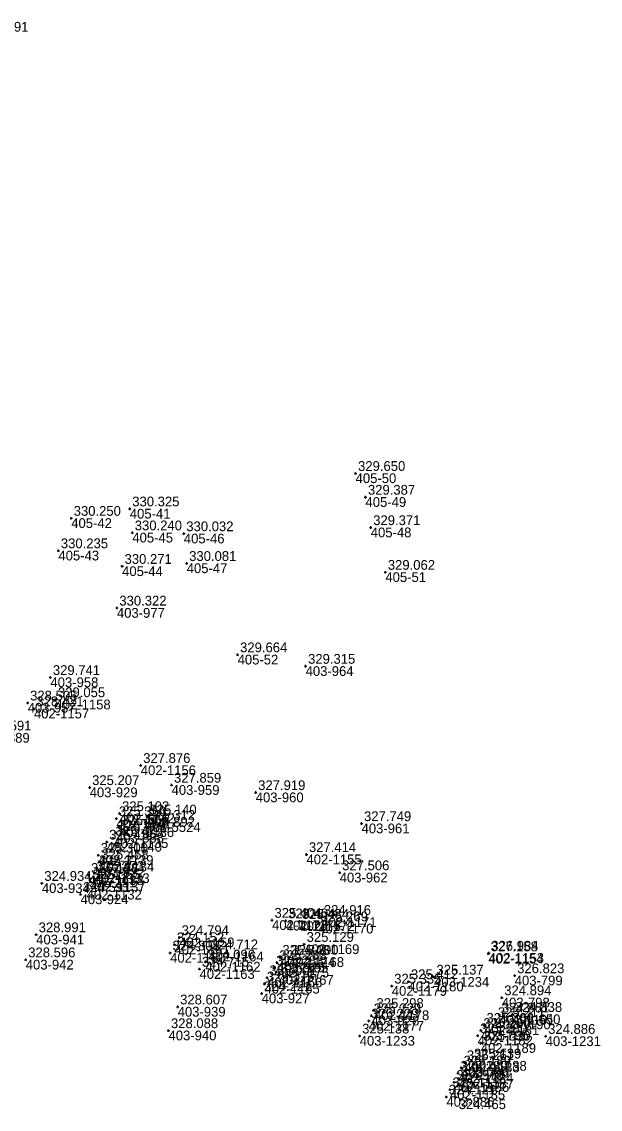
# Model space of a CAD drawing. Extents: x -829398 to -819400, y -1074439 to -1067977.
# Drawn here: x -824965 to -824893.9, y -1069611.4 to -1069477.7 of the extents above; entities that cross this region are included whole.
import ezdxf

# ---------------------------------------------------------------- set-up
doc = ezdxf.new("R2010")
doc.units = 0
for name, color, linetype in [('Vrstva 60', 7, 'Continuous'), ('Vrstva 61', 7, 'Continuous'), ('Čísla bodů_doměření_2012', 7, 'Continuous')]:
    doc.layers.add(name, color=color, linetype=linetype)

# ---------------------------------------------------------------- blocks, each defined once
blk = doc.blocks.new('BOD')
at = {"layer": 'Čísla bodů_doměření_2012'}
for p, q in [((-0.15, 0), (0.15, 0)), ((0, -0.15), (0, 0.15))]:
    blk.add_line(p, q, dxfattribs=at)

msp = doc.modelspace()

# ---------------------------------------------------------------- block references
at = {"layer": 'Vrstva 60'}
for p in [(-824923.944, -1069533.21), (-824922.729, -1069536.135), (-824958.89, -1069538.73), (-824951.691, -1069537.572), (-824922.083, -1069539.875), (-824951.381, -1069540.515), (-824945.052, -1069540.624), (-824960.463, -1069542.719), (-824952.636, -1069544.64), (-824944.7, -1069544.279), (-824920.286, -1069545.369), (-824953.277, -1069549.767), (-824938.442, -1069555.51), (-824930.086, -1069556.926), (-824961.447, -1069558.303), (-824964.242, -1069561.439), (-824960.823, -1069561.033), (-824963.47, -1069562.149), (-824950.345, -1069569.12), (-824956.625, -1069571.838), (-824946.56, -1069571.547), (-824936.219, -1069572.457), (-824953.341, -1069575.664), (-824952.944, -1069575.044), (-824949.774, -1069576.106), (-824949.576, -1069575.457), (-824953.388, -1069577.41), (-824953.034, -1069576.735), (-824923.214, -1069576.272), (-824954.522, -1069578.541), (-824953.741, -1069578.084), (-824955.565, -1069580.17), (-824929.983, -1069580.079), (-824955.475, -1069580.969), (-824956.756, -1069582.639), (-824956.044, -1069582.392), (-824955.76, -1069581.68), (-824925.9, -1069582.316), (-824962.497, -1069583.62), (-824956.541, -1069583.396), (-824957.741, -1069584.984), (-824956.997, -1069584.415), (-824934.213, -1069588.158), (-824928.152, -1069587.802), (-824932.533, -1069588.225), (-824930.853, -1069588.292), (-824928.536, -1069588.591), (-824963.195, -1069589.937), (-824945.617, -1069590.291), (-824946.738, -1069592.18), (-824946.201, -1069591.163), (-824942.036, -1069592.036), (-824930.263, -1069591.121), (-824907.572, -1069592.2), (-824964.477, -1069593.021), (-824942.41, -1069593.281), (-824933.614, -1069593.358), (-824933.239, -1069592.71), (-824932.148, -1069592.708), (-824907.644, -1069592.285), (-824943.126, -1069594.172), (-824933.988, -1069594.006), (-824933.416, -1069594.896), (-824935.137, -1069595.98), (-824934.822, -1069595.217), (-824917.445, -1069595.709), (-824914.307, -1069595.146), (-824904.394, -1069594.974), (-824935.487, -1069597.175), (-824919.498, -1069596.252), (-824945.809, -1069598.814), (-824905.979, -1069597.689), (-824922, -1069599.898), (-824921.678, -1069599.247), (-824906.271, -1069599.808), (-824904.667, -1069599.737), (-824922.323, -1069600.549), (-824908.159, -1069601.072), (-824906.759, -1069600.371), (-824946.936, -1069601.73), (-824923.443, -1069602.39), (-824908.945, -1069602.351), (-824908.552, -1069601.712), (-824900.587, -1069602.436), (-824908.56, -1069603.274), (-824909.692, -1069605.464), (-824910.963, -1069606.314), (-824910.571, -1069605.661), (-824911.848, -1069608.088), (-824911.355, -1069606.967), (-824911.277, -1069607.669), (-824912.35, -1069609.003), (-824912.789, -1069609.885)]:
    msp.add_blockref('BOD', p, dxfattribs=at)

# ---------------------------------------------------------------- texts
for s, p in [('405-50', (-824923.944, -1069534.41)), ('405-49', (-824922.729, -1069537.335)), ('405-41', (-824951.691, -1069538.772)), ('405-42', (-824958.89, -1069539.93)), ('405-48', (-824922.083, -1069541.075)), ('405-45', (-824951.381, -1069541.715)), ('405-46', (-824945.052, -1069541.824)), ('405-43', (-824960.463, -1069543.919)), ('405-44', (-824952.636, -1069545.84)), ('405-47', (-824944.7, -1069545.479)), ('405-51', (-824920.286, -1069546.569)), ('403-977', (-824953.277, -1069550.967)), ('405-52', (-824938.442, -1069556.71)), ('403-964', (-824930.086, -1069558.126)), ('403-958', (-824961.447, -1069559.503)), ('402-1158', (-824960.823, -1069562.233)), ('403-957', (-824964.242, -1069562.639)), ('402-1157', (-824963.47, -1069563.349)), ('403-889', (-824969.883, -1069566.33)), ('402-1156', (-824950.345, -1069570.32)), ('403-929', (-824956.625, -1069573.038)), ('403-959', (-824946.56, -1069572.747)), ('403-960', (-824936.219, -1069573.657)), ('402-1141', (-824953.341, -1069576.864)), ('402-1142', (-824952.944, -1069576.244)), ('403-892', (-824949.576, -1069576.657)), ('402-1136', (-824953.034, -1069577.935)), ('401-5524', (-824949.774, -1069577.306)), ('403-961', (-824923.214, -1069577.472)), ('402-1140', (-824954.522, -1069579.741)), ('402-1135', (-824953.741, -1069579.284)), ('403-888', (-824953.388, -1069578.61)), ('402-1139', (-824955.565, -1069581.37)), ('402-1134', (-824955.475, -1069582.169)), ('402-1155', (-824929.983, -1069581.279)), ('402-1138', (-824956.756, -1069583.839)), ('402-1133', (-824956.044, -1069583.592)), ('403-922', (-824955.76, -1069582.88)), ('403-962', (-824925.9, -1069583.516)), ('403-934', (-824962.497, -1069584.82)), ('402-1137', (-824956.541, -1069584.596)), ('403-924', (-824957.741, -1069586.184)), ('402-1132', (-824956.997, -1069585.615)), ('402-1171', (-824928.152, -1069589.002)), ('402-1173', (-824934.213, -1069589.358)), ('402-1176', (-824932.533, -1069589.425)), ('402-1172', (-824930.853, -1069589.492)), ('402-1170', (-824928.536, -1069589.791)), ('403-941', (-824963.195, -1069591.137)), ('402-1159', (-824945.617, -1069591.491)), ('402-1161', (-824946.201, -1069592.363)), ('402-1164', (-824942.036, -1069593.236)), ('402-1169', (-824930.263, -1069592.321)), ('403-942', (-824964.477, -1069594.221)), ('402-1160', (-824946.738, -1069593.38)), ('402-1162', (-824942.41, -1069594.481)), ('403-925', (-824933.614, -1069594.558)), ('402-1174', (-824933.239, -1069593.91)), ('402-1168', (-824932.148, -1069593.908)), ('402-1154', (-824907.644, -1069593.485)), ('402-1153', (-824907.572, -1069593.4)), ('402-1163', (-824943.126, -1069595.372)), ('402-1175', (-824933.988, -1069595.206)), ('402-1165', (-824935.137, -1069597.18)), ('402-1166', (-824934.822, -1069596.417)), ('402-1167', (-824933.416, -1069596.096)), ('402-1180', (-824917.445, -1069596.909)), ('403-1234', (-824914.307, -1069596.346)), ('403-799', (-824904.394, -1069596.174)), ('403-927', (-824935.487, -1069598.375)), ('402-1179', (-824919.498, -1069597.452)), ('403-798', (-824905.979, -1069598.889)), ('403-939', (-824945.809, -1069600.014)), ('403-928', (-824922, -1069601.098)), ('402-1178', (-824921.678, -1069600.447)), ('402-1191', (-824906.271, -1069601.008)), ('403-650', (-824904.667, -1069600.937)), ('402-1177', (-824922.323, -1069601.749)), ('402-1181', (-824908.159, -1069602.272)), ('402-1190', (-824906.759, -1069601.571)), ('403-940', (-824946.936, -1069602.93)), ('403-1233', (-824923.443, -1069603.59)), ('402-1182', (-824908.945, -1069603.551)), ('403-795', (-824908.552, -1069602.912)), ('403-1231', (-824900.587, -1069603.636)), ('402-1189', (-824908.56, -1069604.474)), ('403-796', (-824910.963, -1069607.514)), ('402-1183', (-824910.571, -1069606.861)), ('402-1188', (-824909.692, -1069606.664)), ('402-1186', (-824911.848, -1069609.288)), ('402-1184', (-824911.355, -1069608.167)), ('402-1187', (-824911.277, -1069608.869)), ('402-1185', (-824912.35, -1069610.203)), ('403-886', (-824912.789, -1069611.085))]:
    msp.add_text(s, height=1.2, dxfattribs=at).set_placement(p)
at = {"layer": 'Vrstva 61'}
for s, p in [('326.591', (-824969.946, -1069478.898)), ('329.650', (-824923.644, -1069532.91)), ('329.387', (-824922.429, -1069535.835)), ('330.250', (-824958.59, -1069538.43)), ('330.325', (-824951.391, -1069537.272)), ('329.371', (-824921.783, -1069539.575)), ('330.240', (-824951.081, -1069540.215)), ('330.032', (-824944.752, -1069540.324)), ('330.235', (-824960.163, -1069542.419)), ('330.271', (-824952.336, -1069544.34)), ('330.081', (-824944.4, -1069543.979)), ('329.062', (-824919.986, -1069545.069)), ('330.322', (-824952.977, -1069549.467)), ('329.664', (-824938.142, -1069555.21)), ('329.315', (-824929.786, -1069556.626)), ('329.741', (-824961.147, -1069558.003)), ('328.505', (-824963.942, -1069561.139)), ('329.055', (-824960.523, -1069560.733)), ('328.421', (-824963.17, -1069561.849)), ('325.591', (-824969.583, -1069564.83)), ('327.876', (-824950.045, -1069568.82)), ('325.207', (-824956.325, -1069571.538)), ('327.859', (-824946.26, -1069571.247)), ('327.919', (-824935.919, -1069572.157)), ('325.350', (-824953.041, -1069575.364)), ('325.102', (-824952.644, -1069574.744)), ('325.312', (-824949.474, -1069575.806)), ('325.140', (-824949.276, -1069575.157)), ('325.479', (-824953.088, -1069577.11)), ('325.565', (-824952.734, -1069576.435)), ('327.749', (-824922.914, -1069575.972)), ('325.186', (-824954.222, -1069578.241)), ('325.479', (-824953.441, -1069577.784)), ('325.300', (-824955.265, -1069579.87)), ('327.414', (-824929.683, -1069579.779)), ('325.458', (-824955.175, -1069580.669)), ('325.198', (-824956.456, -1069582.339)), ('325.373', (-824955.744, -1069582.092)), ('325.373', (-824955.46, -1069581.38)), ('327.506', (-824925.6, -1069582.016)), ('324.934', (-824962.197, -1069583.32)), ('325.065', (-824956.241, -1069583.096)), ('324.591', (-824957.441, -1069584.684)), ('325.291', (-824956.697, -1069584.115)), ('325.404', (-824933.913, -1069587.858)), ('325.404', (-824932.233, -1069587.925)), ('324.916', (-824927.852, -1069587.502)), ('325.484', (-824930.553, -1069587.992)), ('325.269', (-824928.236, -1069588.291)), ('328.991', (-824962.895, -1069589.637)), ('324.794', (-824945.317, -1069589.991)), ('324.808', (-824946.438, -1069591.88)), ('324.152', (-824945.901, -1069590.863)), ('324.712', (-824941.736, -1069591.736)), ('325.129', (-824929.963, -1069590.821)), ('326.984', (-824907.272, -1069591.9)), ('328.596', (-824964.177, -1069592.721)), ('324.096', (-824942.11, -1069592.981)), ('325.283', (-824933.314, -1069593.058)), ('325.348', (-824932.939, -1069592.41)), ('325.200', (-824931.848, -1069592.408)), ('327.158', (-824907.344, -1069591.985)), ('324.715', (-824942.826, -1069593.872)), ('325.283', (-824933.688, -1069593.706)), ('325.105', (-824933.116, -1069594.596)), ('325.175', (-824934.837, -1069595.68)), ('325.001', (-824934.522, -1069594.917)), ('325.335', (-824919.198, -1069595.952)), ('325.412', (-824917.145, -1069595.409)), ('325.137', (-824914.007, -1069594.846)), ('326.823', (-824904.094, -1069594.674)), ('324.221', (-824935.187, -1069596.875)), ('328.607', (-824945.509, -1069598.514)), ('324.894', (-824905.679, -1069597.389)), ('325.229', (-824921.7, -1069599.598)), ('325.298', (-824921.378, -1069598.947)), ('324.861', (-824905.971, -1069599.508)), ('324.838', (-824904.367, -1069599.437)), ('325.229', (-824922.023, -1069600.249)), ('325.366', (-824907.859, -1069600.772)), ('325.211', (-824906.459, -1069600.071)), ('328.088', (-824946.636, -1069601.43)), ('325.138', (-824923.143, -1069602.09)), ('325.280', (-824908.645, -1069602.051)), ('325.280', (-824908.252, -1069601.412)), ('324.886', (-824900.287, -1069602.136)), ('325.030', (-824908.26, -1069602.974)), ('325.139', (-824909.392, -1069605.164)), ('325.189', (-824910.663, -1069606.014)), ('325.261', (-824910.271, -1069605.361)), ('324.975', (-824911.548, -1069607.788)), ('325.189', (-824911.055, -1069606.667)), ('325.020', (-824910.977, -1069607.369)), ('325.113', (-824912.05, -1069608.703)), ('324.121', (-824912.489, -1069609.585)), ('324.465', (-824911.271, -1069611.388))]:
    msp.add_text(s, height=1.2, dxfattribs=at).set_placement(p)

doc.saveas('drawing.dxf')
